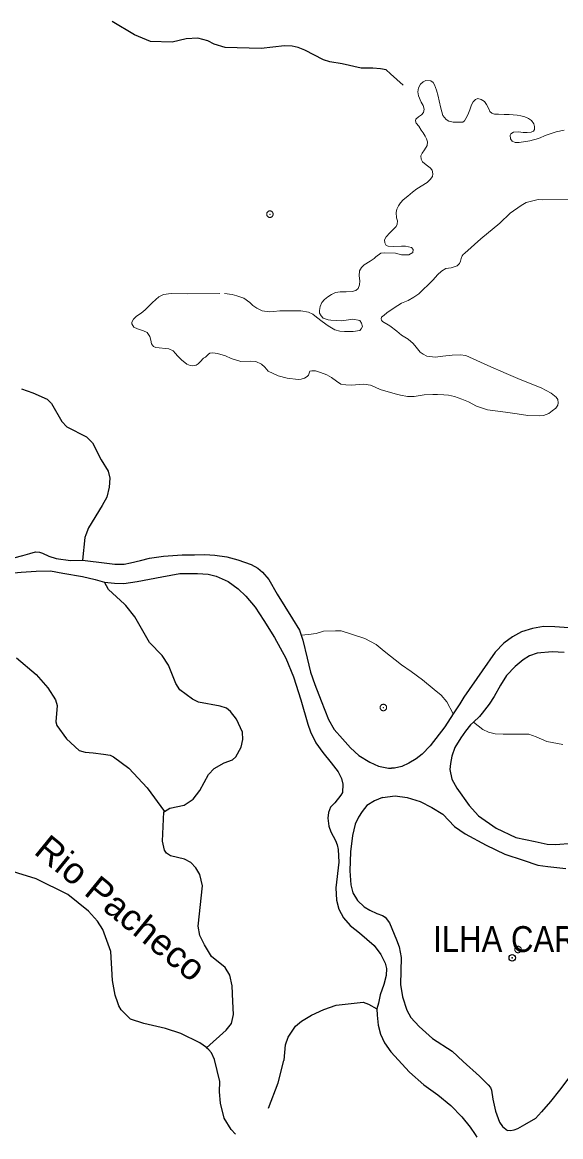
# Model space of a CAD drawing. Extents: x 267.7 to 296, y 7537.7 to 7565.8.
# Drawn here: x 278.742 to 280.408, y 7555.949 to 7559.393 of the extents above; entities that cross this region are included whole.
import ezdxf
from ezdxf.enums import TextEntityAlignment as Align

# ---------------------------------------------------------------- set-up
doc = ezdxf.new("R2010")
doc.units = 0
doc.header["$LTSCALE"] = 0.04
doc.header["$PDMODE"] = 32
doc.header["$PDSIZE"] = 0.02
doc.linetypes.add('SHORT_DASHED', pattern=[2.7, 1.5, -1.2])
for name, color, linetype, lineweight in [('2', 7, 'Continuous', 25), ('21', 7, 'SHORT_DASHED', 13), ('7', 7, 'Continuous', 25)]:
    doc.layers.add(name, color=color, linetype=linetype, lineweight=lineweight)
doc.layers.add('54', color=7, linetype='Continuous')
doc.layers.add('61', color=7, linetype='Continuous')

msp = doc.modelspace()

# ---------------------------------------------------------------- linework, layer by layer
at = {"layer": '2'}
for points in [[(278.4224, 7557.8335), (278.4371, 7557.7994), (278.4631, 7557.7544), (278.4809, 7557.7289), (278.4963, 7557.7164), (278.5313, 7557.6999), (278.5561, 7557.6933), (278.5822, 7557.688), (278.6325, 7557.6845), (278.7392, 7557.6939), (278.7848, 7557.6969), (278.8298, 7557.6981), (278.8677, 7557.6904), (278.9281, 7557.6803), (278.9672, 7557.6708), (278.9966, 7557.6627)], [(278.716, 7557.7384), (278.7437, 7557.7448), (278.765, 7557.7512), (278.7826, 7557.756), (278.7959, 7557.7554), (278.8044, 7557.7528), (278.8247, 7557.7427), (278.847, 7557.7363), (278.8918, 7557.7299), (278.9283, 7557.7312)], [(278.9283, 7557.7312), (279.0037, 7557.7219), (279.0282, 7557.7187), (279.0575, 7557.7181), (279.0772, 7557.7229), (279.1081, 7557.7299), (279.1352, 7557.7368), (279.1795, 7557.7432), (279.237, 7557.7469), (279.2748, 7557.7474), (279.3068, 7557.7485), (279.3377, 7557.7458), (279.375, 7557.7411), (279.4091, 7557.7315), (279.4501, 7557.7171), (279.4709, 7557.7059), (279.4853, 7557.6936), (279.5044, 7557.6707), (279.5305, 7557.6254), (279.5785, 7557.5498), (279.5993, 7557.5141), (279.6049, 7557.4987)], [(278.9966, 7557.6627), (279.027, 7557.6596), (279.0566, 7557.659), (279.0975, 7557.6643), (279.1739, 7557.6791), (279.2296, 7557.6898), (279.2841, 7557.6898), (279.3173, 7557.6874), (279.3416, 7557.6815), (279.3795, 7557.6643), (279.4097, 7557.6424), (279.434, 7557.6199), (279.463, 7557.585), (279.489, 7557.5441), (279.5228, 7557.492), (279.5578, 7557.4274), (279.5809, 7557.3699), (279.604, 7557.2995), (279.6259, 7557.2236), (279.6342, 7557.1999), (279.6507, 7557.1662), (279.6715, 7557.1366), (279.6975, 7557.104), (279.7189, 7557.0767), (279.7301, 7557.0554), (279.7337, 7557.0388), (279.7331, 7557.0128), (279.7277, 7557.0039), (279.7094, 7556.9802), (279.6958, 7556.9678), (279.6892, 7556.9512), (279.6875, 7556.9328), (279.691, 7556.9085), (279.6969, 7556.8907), (279.7112, 7556.8641), (279.7165, 7556.8505), (279.7195, 7556.8363), (279.7212, 7556.7978), (279.7118, 7556.7178), (279.7141, 7556.6799), (279.7212, 7556.652), (279.7354, 7556.6254), (279.7568, 7556.6011), (279.7858, 7556.5786), (279.8308, 7556.5395), (279.8515, 7556.5123), (279.8646, 7556.485), (279.8693, 7556.469), (279.8681, 7556.4465), (279.861, 7556.4187), (279.8492, 7556.3873), (279.8438, 7556.3612), (279.8394, 7556.3441)], [(279.6049, 7557.4987), (279.6105, 7557.4832), (279.6232, 7557.4278), (279.6339, 7557.3846), (279.6467, 7557.3463), (279.6669, 7557.2957), (279.6893, 7557.2387), (279.7069, 7557.2072), (279.7324, 7557.179), (279.7575, 7557.1502), (279.7831, 7557.1268), (279.8172, 7557.106), (279.8443, 7557.0938), (279.8747, 7557.0874), (279.884, 7557.0874)], [(280.4627, 7557.5192), (280.3899, 7557.5242), (280.3547, 7557.5253), (280.3201, 7557.5194), (280.287, 7557.5093), (280.2588, 7557.4933), (280.2322, 7557.4741), (280.2055, 7557.4464), (280.165, 7557.3889), (280.1086, 7557.3074), (280.0956, 7557.2871), (280.0755, 7557.2557)], [(280.4187, 7557.4457), (280.3811, 7557.4477), (280.3345, 7557.4429), (280.3112, 7557.4354), (280.2913, 7557.4224), (280.2674, 7557.4018), (280.24, 7557.3738), (280.2215, 7557.3443), (280.2023, 7557.3094), (280.1865, 7557.2854), (280.1652, 7557.2581), (280.1571, 7557.2477), (280.1379, 7557.2299)], [(280.0755, 7557.2557), (280.0494, 7557.2158), (280.0036, 7557.1566), (279.9791, 7557.1316), (279.961, 7557.1167), (279.9381, 7557.1028), (279.9168, 7557.0932), (279.8933, 7557.0874), (279.884, 7557.0874)], [(280.1379, 7557.2299), (280.129, 7557.2217), (280.1133, 7557.2025), (280.0989, 7557.182), (280.0804, 7557.1512), (280.0708, 7557.1245), (280.0667, 7557.1019), (280.0653, 7557.0834), (280.0708, 7557.0539)], [(280.0708, 7557.0539), (280.0866, 7557.0265), (280.1242, 7556.9724), (280.1537, 7556.9402), (280.2078, 7556.9026), (280.2695, 7556.8738), (280.3286, 7556.8607), (280.366, 7556.8532), (280.3913, 7556.8522), (280.4447, 7556.856)], [(279.8565, 7556.9974), (279.8314, 7556.9873), (279.8083, 7556.9723), (279.7933, 7556.9542), (279.7822, 7556.9361), (279.7722, 7556.915), (279.7641, 7556.8799), (279.7571, 7556.8297), (279.7551, 7556.7704), (279.7581, 7556.7272), (279.7651, 7556.7021), (279.7792, 7556.679), (279.7993, 7556.6589), (279.8174, 7556.6489), (279.8395, 7556.6388), (279.8565, 7556.6328), (279.8646, 7556.6278), (279.8786, 7556.6097), (279.8997, 7556.5575), (279.9077, 7556.5354), (279.9138, 7556.5022), (279.9118, 7556.4189), (279.9188, 7556.3807), (279.9319, 7556.3396), (279.9439, 7556.3175), (279.97, 7556.2893), (280.0112, 7556.2522), (280.0725, 7556.213), (280.1056, 7556.1809), (280.1568, 7556.1357), (280.1829, 7556.1096), (280.191, 7556.1005), (280.194, 7556.0925), (280.198, 7556.0644), (280.206, 7556.0272), (280.2181, 7555.9941), (280.2281, 7555.98), (280.2432, 7555.968)], [(279.8565, 7556.9974), (279.8957, 7557.0024), (279.9329, 7556.9974), (279.973, 7556.9853), (280.0092, 7556.9662), (280.0433, 7556.9452), (280.0795, 7556.908), (280.1126, 7556.8849), (280.1769, 7556.8497), (280.2352, 7556.8216), (280.2914, 7556.8035), (280.3366, 7556.7885), (280.3677, 7556.7835), (280.424, 7556.7774)], [(279.8394, 7556.3441), (279.8397, 7556.3239), (279.8433, 7556.2931), (279.8504, 7556.2658), (279.8622, 7556.2386), (279.8823, 7556.2114), (279.9398, 7556.1486), (279.9848, 7556.1089), (280.0281, 7556.0787), (280.0677, 7556.0449), (280.1021, 7556.0106), (280.1282, 7555.978), (280.1436, 7555.9561), (280.1483, 7555.9472)], [(280.442, 7556.1427), (280.4039, 7556.0925), (280.3758, 7556.0573), (280.3486, 7556.0252), (280.3296, 7556.0051), (280.2954, 7555.985), (280.2743, 7555.973), (280.2633, 7555.969), (280.2532, 7555.967), (280.2432, 7555.968)]]:
    msp.add_lwpolyline(points, dxfattribs=at)
at = {"layer": '21'}
for points in [[(279.9461, 7558.6974), (279.9276, 7558.7007), (279.9153, 7558.7007), (279.8901, 7558.7002), (279.8745, 7558.7007), (279.8683, 7558.7035), (279.8636, 7558.7111), (279.8631, 7558.7206), (279.8679, 7558.7301), (279.8797, 7558.7419), (279.8897, 7558.7523), (279.8987, 7558.7623), (279.9015, 7558.7694), (279.9025, 7558.7794), (279.9001, 7558.7888), (279.8987, 7558.805), (279.9006, 7558.8159), (279.9058, 7558.8263), (279.9124, 7558.8353), (279.92, 7558.8448), (279.9347, 7558.8562), (279.9418, 7558.8618), (279.9489, 7558.8685), (279.9631, 7558.878), (279.9949, 7558.8983), (280.0044, 7558.9069), (280.0115, 7558.9163), (280.0124, 7558.9244), (280.0101, 7558.9358), (280.0044, 7558.9429), (279.992, 7558.9524), (279.9807, 7558.9614), (279.9759, 7558.9704), (279.9755, 7558.9803), (279.9797, 7558.9889), (279.9868, 7558.9993), (279.9944, 7559.0126), (279.9958, 7559.0239), (279.993, 7559.0334), (279.9887, 7559.0415), (279.9826, 7559.0514), (279.9759, 7559.0595), (279.9688, 7559.0718), (279.9608, 7559.0813), (279.9589, 7559.0889), (279.9598, 7559.0941), (279.9674, 7559.1007), (279.9769, 7559.1069), (279.9835, 7559.1145), (279.9854, 7559.1244), (279.9826, 7559.1358), (279.9764, 7559.1462), (279.9674, 7559.1661), (279.966, 7559.1785), (279.9679, 7559.1908), (279.9736, 7559.2017), (279.9821, 7559.2093), (279.9906, 7559.2131), (280.0058, 7559.2121), (280.0134, 7559.2074), (280.0172, 7559.2003), (280.0238, 7559.1837), (280.0285, 7559.1647), (280.0314, 7559.15), (280.0371, 7559.1282), (280.0432, 7559.1055), (280.0532, 7559.0932), (280.0617, 7559.0879), (280.075, 7559.0846), (280.1053, 7559.0846), (280.1101, 7559.0889), (280.1148, 7559.096), (280.12, 7559.1074), (280.1262, 7559.1225), (280.1319, 7559.1377), (280.1366, 7559.1472), (280.1442, 7559.1548), (280.1513, 7559.1571), (280.1622, 7559.1548), (280.1722, 7559.1481), (280.1783, 7559.1391), (280.185, 7559.1254), (280.1883, 7559.1173), (280.1944, 7559.1121), (280.203, 7559.1093), (280.2158, 7559.1088), (280.2324, 7559.1083), (280.2485, 7559.1083), (280.2731, 7559.1064), (280.284, 7559.1045), (280.2968, 7559.1007), (280.3077, 7559.096), (280.3172, 7559.0894), (280.3243, 7559.0794), (280.3267, 7559.0713)], [(280.2916, 7559.0529), (280.2769, 7559.0543), (280.2622, 7559.0533), (280.2532, 7559.0481), (280.2513, 7559.0443), (280.2527, 7559.0325), (280.258, 7559.0258), (280.267, 7559.0221), (280.2788, 7559.0216), (280.3125, 7559.0263), (280.3395, 7559.0344), (280.3627, 7559.0439), (280.3935, 7559.0548), (280.4182, 7559.06)], [(280.3267, 7559.0713), (280.3272, 7559.0614), (280.3234, 7559.0562), (280.3167, 7559.0538), (280.3044, 7559.0524), (280.2916, 7559.0529)], [(280.0943, 7558.6472), (280.0982, 7558.6544), (280.0998, 7558.6631), (280.1031, 7558.6714), (280.1064, 7558.6757), (280.1113, 7558.6796), (280.1612, 7558.724), (280.2193, 7558.7728), (280.2511, 7558.8029), (280.2851, 7558.8271), (280.3005, 7558.8358), (280.3131, 7558.8397), (280.3377, 7558.8451), (280.3509, 7558.8446), (280.4331, 7558.8451)], [(279.318, 7558.3676), (279.3087, 7558.3583), (279.3027, 7558.355), (279.2928, 7558.3441), (279.2862, 7558.338), (279.2796, 7558.3336), (279.2681, 7558.3314), (279.2616, 7558.332), (279.2517, 7558.3366), (279.2346, 7558.3499), (279.2227, 7558.3618), (279.2161, 7558.3698), (279.2085, 7558.3779), (279.1952, 7558.3836), (279.155, 7558.3878), (279.1478, 7558.3916), (279.1422, 7558.3997), (279.1398, 7558.4111), (279.1365, 7558.4224), (279.1284, 7558.4343), (279.117, 7558.44), (279.0986, 7558.4452), (279.0876, 7558.4509), (279.081, 7558.4608), (279.081, 7558.466), (279.0858, 7558.4755), (279.0952, 7558.4845), (279.1095, 7558.4945), (279.1223, 7558.5049), (279.1336, 7558.5153), (279.1436, 7558.5258), (279.155, 7558.5367), (279.1649, 7558.5447), (279.1791, 7558.5523), (279.2024, 7558.5552), (279.2536, 7558.5542), (279.3673, 7558.5547), (279.3915, 7558.5523), (279.4062, 7558.5481), (279.428, 7558.5405), (279.446, 7558.5272), (279.4555, 7558.5182), (279.4673, 7558.5092), (279.4844, 7558.5011), (279.5071, 7558.4983), (279.5195, 7558.4988), (279.5389, 7558.5011), (279.6038, 7558.5011), (279.6275, 7558.4969), (279.6413, 7558.4912), (279.6527, 7558.4822), (279.6697, 7558.4684), (279.6882, 7558.4547), (279.7086, 7558.4423), (279.7247, 7558.4381), (279.7394, 7558.4371), (279.7659, 7558.4371), (279.7859, 7558.4405), (279.7906, 7558.4452), (279.7944, 7558.4533), (279.7915, 7558.4637), (279.7859, 7558.4717), (279.765, 7558.4751), (279.7441, 7558.4722), (279.7294, 7558.4703), (279.6963, 7558.4722), (279.6887, 7558.4736), (279.673, 7558.4788), (279.6664, 7558.486), (279.6621, 7558.4945), (279.6621, 7558.5025), (279.664, 7558.5144), (279.6692, 7558.5272), (279.6768, 7558.5362), (279.6877, 7558.5447), (279.6986, 7558.5518), (279.711, 7558.5575), (279.7257, 7558.5599), (279.7437, 7558.5604), (279.7622, 7558.5613), (279.7745, 7558.5642), (279.7811, 7558.5699), (279.7854, 7558.5812), (279.7859, 7558.594), (279.784, 7558.6092), (279.7849, 7558.6248), (279.7911, 7558.6357), (279.7996, 7558.6438), (279.8186, 7558.6552), (279.8304, 7558.6632), (279.8361, 7558.6684), (279.8513, 7558.6793), (279.8641, 7558.6808), (279.8972, 7558.6798), (279.9153, 7558.6746)], [(279.9153, 7558.6746), (279.9281, 7558.6741), (279.938, 7558.6741), (279.9499, 7558.6812), (279.9513, 7558.6912), (279.9461, 7558.6974)], [(280.0263, 7558.6121), (280.039, 7558.6242), (280.0521, 7558.6319), (280.0686, 7558.6341), (280.0872, 7558.6407), (280.0943, 7558.6472)], [(279.318, 7558.3676), (279.3219, 7558.3704), (279.3312, 7558.372), (279.3465, 7558.3693), (279.3712, 7558.3627), (279.3882, 7558.3539), (279.4178, 7558.3452), (279.4469, 7558.3457), (279.465, 7558.3446), (279.4819, 7558.3369), (279.4929, 7558.3276), (279.5028, 7558.315), (279.5335, 7558.3007), (279.562, 7558.2936), (279.596, 7558.2892), (279.6048, 7558.2898), (279.6157, 7558.2931), (279.6234, 7558.2986), (279.6272, 7558.3029), (279.6294, 7558.309), (279.6322, 7558.315), (279.6382, 7558.3161), (279.6492, 7558.3161), (279.6645, 7558.3106), (279.6848, 7558.3035), (279.6985, 7558.2953), (279.7139, 7558.2843), (279.7281, 7558.275), (279.7435, 7558.2722), (279.761, 7558.2711), (279.7983, 7558.2744), (279.8197, 7558.2717), (279.8339, 7558.2657), (279.8493, 7558.258), (279.8959, 7558.2448), (279.9123, 7558.2404), (279.9337, 7558.2366), (279.9474, 7558.2361), (279.9545, 7558.2361), (279.9852, 7558.2421), (280.0121, 7558.2426), (280.0263, 7558.2432), (280.0461, 7558.2421), (280.0603, 7558.241), (280.079, 7558.2361), (280.1015, 7558.2284), (280.1228, 7558.2202), (280.147, 7558.207), (280.1815, 7558.1955), (280.2374, 7558.1884), (280.2736, 7558.1829), (280.3059, 7558.1774), (280.341, 7558.1763), (280.3542, 7558.1779), (280.3712, 7558.184), (280.3816, 7558.1922), (280.3926, 7558.2004), (280.3986, 7558.2097), (280.3997, 7558.2169), (280.3986, 7558.2273), (280.3937, 7558.235), (280.3778, 7558.247), (280.3471, 7558.2635), (280.2829, 7558.2887), (280.2391, 7558.3073), (280.182, 7558.3325), (280.1146, 7558.3632), (280.0965, 7558.3649), (280.0719, 7558.3643), (280.0433, 7558.3616), (280.0209, 7558.3583), (279.994, 7558.3611), (279.9819, 7558.3671), (279.9732, 7558.3737), (279.9606, 7558.389), (279.9518, 7558.4), (279.9359, 7558.4137), (279.9156, 7558.4263), (279.9008, 7558.4389), (279.8789, 7558.4548), (279.8569, 7558.4685), (279.8531, 7558.4729), (279.8526, 7558.4767), (279.8537, 7558.4822), (279.8613, 7558.4877), (279.8696, 7558.4948), (279.8931, 7558.5107), (279.9156, 7558.525), (279.9359, 7558.5337), (279.9534, 7558.5431), (279.9688, 7558.554), (279.9836, 7558.5688), (279.9967, 7558.5809), (280.0132, 7558.5968), (280.0263, 7558.6121)], [(279.6049, 7557.4987), (279.6277, 7557.5007), (279.6511, 7557.5037), (279.6744, 7557.511), (279.711, 7557.5124), (279.7285, 7557.5124), (279.8016, 7557.489), (279.8367, 7557.47), (279.8616, 7557.4496), (279.9157, 7557.4072), (279.9449, 7557.3867), (279.98, 7557.3604), (280.0165, 7557.3312), (280.0385, 7557.3136), (280.056, 7557.2931), (280.0755, 7557.2557)], [(280.1379, 7557.2299), (280.1672, 7557.207), (280.1848, 7557.1987), (280.2051, 7557.1941), (280.2301, 7557.1931), (280.2652, 7557.1931), (280.2818, 7557.1931), (280.3096, 7557.1931), (280.3317, 7557.1848), (280.365, 7557.17), (280.414, 7557.1608)]]:
    msp.add_lwpolyline(points, dxfattribs=at)
for p in [(279.5082, 7558.8001), (279.8592, 7557.2753), (280.2758, 7556.5273)]:
    msp.add_point(p, dxfattribs=at)
at = {"layer": '54'}
msp.add_point((280.258, 7556.5018), dxfattribs=at)
at = {"layer": '7'}
for points in [[(279.9209, 7559.1985), (279.8809, 7559.2335), (279.8675, 7559.2457), (279.85, 7559.2498), (279.8264, 7559.251), (279.7904, 7559.2515), (279.732, 7559.2652), (279.6934, 7559.2707), (279.6738, 7559.277), (279.6159, 7559.3071), (279.5955, 7559.3155), (279.5768, 7559.3193), (279.5529, 7559.3205), (279.4811, 7559.3119), (279.3697, 7559.3148), (279.3354, 7559.3252), (279.3165, 7559.3363), (279.285, 7559.3443), (279.2495, 7559.3417), (279.2063, 7559.3316), (279.139, 7559.3338), (279.0897, 7559.3542), (279.0197, 7559.3957)], [(278.7393, 7558.2601), (278.7752, 7558.2479), (278.8194, 7558.228), (278.8321, 7558.2145), (278.8646, 7558.1589), (278.8803, 7558.1425), (278.9409, 7558.1119), (278.9598, 7558.0937), (278.9865, 7558.0403), (279.0074, 7558.0058), (279.0135, 7557.9842), (279.0108, 7557.9566), (279.0033, 7557.9257), (278.9891, 7557.8996), (278.9467, 7557.8303), (278.9392, 7557.8094), (278.9361, 7557.8008), (278.9283, 7557.7312)], [(279.1822, 7556.9542), (279.1985, 7556.9642), (279.2431, 7556.9733), (279.2713, 7556.9922), (279.2912, 7557.0189), (279.3178, 7557.0684), (279.3357, 7557.0864), (279.3662, 7557.1043), (279.3923, 7557.1139), (279.403, 7557.1227), (279.4192, 7557.1524), (279.4241, 7557.1763), (279.4233, 7557.1989), (279.4044, 7557.239), (279.3863, 7557.2628), (279.3742, 7557.2733), (279.3545, 7557.2797), (279.2871, 7557.2916), (279.2686, 7557.3011), (279.2299, 7557.3299), (279.2173, 7557.349), (279.1945, 7557.4062), (279.1751, 7557.4362), (279.1356, 7557.4759), (279.0903, 7557.5559), (279.0625, 7557.5908), (279.0585, 7557.5944), (279.0084, 7557.6396), (278.9966, 7557.6627)], [(278.7241, 7557.4289), (278.7846, 7557.3772), (278.8212, 7557.3362), (278.8449, 7557.2995), (278.8501, 7557.2819), (278.8459, 7557.2314), (278.8486, 7557.2196), (278.8787, 7557.1783), (278.9178, 7557.1427), (278.9367, 7557.1369), (278.9612, 7557.1354), (278.9936, 7557.131), (279.014, 7557.1281), (279.0244, 7557.1229), (279.072, 7557.0879), (279.1285, 7557.0272), (279.1822, 7556.9542)], [(279.3121, 7556.2237), (279.3732, 7556.2782), (279.389, 7556.2986), (279.3958, 7556.3268), (279.3938, 7556.3663), (279.3912, 7556.4154), (279.3844, 7556.4477), (279.3696, 7556.472), (279.3273, 7556.5058), (279.3054, 7556.5413), (279.2914, 7556.571), (279.286, 7556.5995), (279.2995, 7556.7237), (279.2918, 7556.7588), (279.2793, 7556.7797), (279.2633, 7556.7962), (279.2435, 7556.807), (279.2002, 7556.8166), (279.1881, 7556.8255), (279.1816, 7556.8346), (279.1756, 7556.8622), (279.1798, 7556.9527), (279.1822, 7556.9542)], [(279.3121, 7556.2237), (279.3117, 7556.2241), (279.2916, 7556.2386), (279.2323, 7556.268), (279.1856, 7556.283), (279.1179, 7556.2984), (279.0773, 7556.3123), (279.0484, 7556.3407), (279.0405, 7556.3529), (279.0373, 7556.3628), (279.0297, 7556.3858), (279.0208, 7556.432), (279.0158, 7556.5208), (278.9912, 7556.5887), (278.9745, 7556.6147), (278.9467, 7556.6462), (278.8833, 7556.6969), (278.7849, 7556.746), (278.6707, 7556.7803)], [(279.5039, 7556.037), (279.5341, 7556.1157), (279.5514, 7556.1844), (279.5518, 7556.1858), (279.5569, 7556.2328), (279.5646, 7556.2567), (279.5871, 7556.2904), (279.6055, 7556.3062), (279.6368, 7556.3247), (279.6746, 7556.342), (279.7127, 7556.355), (279.7962, 7556.3644), (279.8136, 7556.3586), (279.8394, 7556.3441)], [(279.4018, 7555.9568), (279.3884, 7555.9706), (279.3663, 7556.0059), (279.3555, 7556.0528), (279.3522, 7556.0874), (279.3534, 7556.1196), (279.3366, 7556.1877), (279.3276, 7556.2081), (279.3196, 7556.2176), (279.3121, 7556.2237)]]:
    msp.add_lwpolyline(points, dxfattribs=at)

# ---------------------------------------------------------------- texts
at = {"layer": '54', "width": 0.9}
msp.add_text('ILHA CARAPEBA', height=0.08, dxfattribs=at).set_placement((280.0132, 7556.5196))
at = {"layer": '61', "width": 1.05}
msp.add_text('Rio Pacheco', height=0.08, rotation=320.8, dxfattribs=at).set_placement((279.0212, 7556.6244), align=Align.CENTER)

doc.saveas('drawing.dxf')
